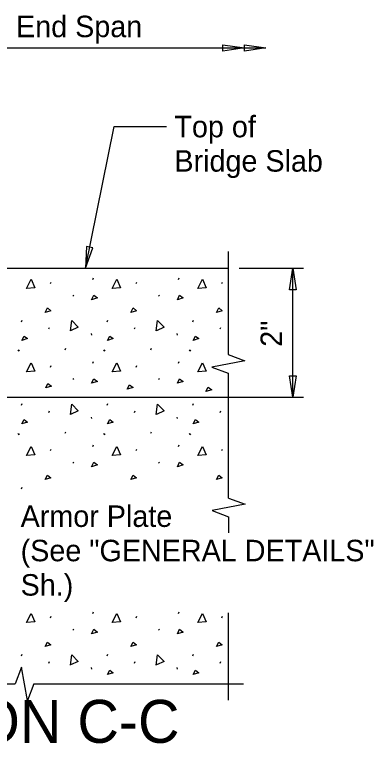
# Model space of a CAD drawing. Extents: x 2799.7 to 2896, y 515.2 to 573.9.
# Drawn here: x 2841.51 to 2847.07, y 530.53 to 541.84 of the extents above; entities that cross this region are included whole.
import ezdxf

# ---------------------------------------------------------------- set-up
doc = ezdxf.new("R2010")
doc.units = 0
for name, color, linetype in [('BR_AUTO DIMENSION', 7, 'Continuous'), ('BR_CONCRETE', 7, 'Continuous'), ('BR_DETAILS', 7, 'Continuous'), ('BR_TEXT', 7, 'Continuous')]:
    doc.layers.add(name, color=color, linetype=linetype)

# ---------------------------------------------------------------- blocks, each defined once
blk = doc.blocks.new('B')
at = {"layer": 'BR_AUTO DIMENSION'}
blk.add_lwpolyline([(-0.2, 0.03), (0, 0), (-0.2, -0.03)], close=True, dxfattribs=at)
blk = doc.blocks.new('ARROW')
at = {"layer": 'BR_AUTO DIMENSION', "xscale": 0.625, "yscale": 0.625}
blk.add_blockref('B', (0, 0), dxfattribs=at)
blk = doc.blocks.new('DAH')
at = {"layer": 'BR_AUTO DIMENSION'}
for p in [(-0.1248, 0), (0, 0)]:
    blk.add_blockref('ARROW', p, dxfattribs=at)

msp = doc.modelspace()

# ---------------------------------------------------------------- linework, layer by layer
at = {"layer": 'BR_AUTO DIMENSION'}
for p, q in [((2834.103, 541.324), (2845.404, 541.324)), ((2842.603, 537.904), (2843.05, 540.103)), ((2843.05, 540.103), (2843.863, 540.103)), ((2844.988, 537.904), (2845.988, 537.904)), ((2845.822, 535.904), (2845.822, 537.904)), ((2840.067, 535.904), (2845.988, 535.904))]:
    msp.add_line(p, q, dxfattribs=at)
for points in [[(2842.62, 538.241), (2842.603, 537.904), (2842.718, 538.221)], [(2845.772, 537.571), (2845.822, 537.904), (2845.872, 537.571)], [(2845.872, 536.237), (2845.822, 535.904), (2845.772, 536.237)]]:
    msp.add_lwpolyline(points, close=True, dxfattribs=at)
at = {"layer": 'BR_CONCRETE'}
msp.add_line((2840.567, 537.904), (2844.821, 537.904), dxfattribs=at)
at = {"layer": 'BR_DETAILS'}
for p, q in [((2844.821, 538.167), (2844.821, 536.565)), ((2842.063, 537.667), (2842.074, 537.691)), ((2842.721, 537.73), (2842.732, 537.755)), ((2843.392, 537.667), (2843.403, 537.691)), ((2844.05, 537.73), (2844.061, 537.755)), ((2844.722, 537.667), (2844.733, 537.691)), ((2842.41, 537.489), (2842.421, 537.472)), ((2843.739, 537.489), (2843.75, 537.472)), ((2841.613, 537.075), (2841.624, 537.1)), ((2842.943, 537.075), (2842.954, 537.1)), ((2844.272, 537.075), (2844.283, 537.1)), ((2842.035, 536.962), (2842.046, 536.987)), ((2843.365, 536.962), (2843.376, 536.987)), ((2844.694, 536.962), (2844.705, 536.987)), ((2842.695, 536.892), (2842.698, 536.867)), ((2844.024, 536.892), (2844.027, 536.867)), ((2841.555, 536.64), (2841.566, 536.623)), ((2841.566, 536.633), (2841.577, 536.617)), ((2842.288, 536.64), (2842.299, 536.665)), ((2842.884, 536.64), (2842.895, 536.623)), ((2842.895, 536.633), (2842.907, 536.617)), ((2843.617, 536.64), (2843.628, 536.665)), ((2844.214, 536.64), (2844.225, 536.623)), ((2844.225, 536.633), (2844.236, 536.617)), ((2842.721, 536.434), (2842.732, 536.459)), ((2844.05, 536.434), (2844.061, 536.459)), ((2842.063, 536.37), (2842.074, 536.395)), ((2843.392, 536.37), (2843.403, 536.395)), ((2842.41, 536.193), (2842.421, 536.176)), ((2843.739, 536.193), (2843.75, 536.176)), ((2844.821, 536.275), (2844.821, 534.337)), ((2841.613, 535.779), (2841.624, 535.804)), ((2842.943, 535.779), (2842.954, 535.804)), ((2844.272, 535.779), (2844.283, 535.804)), ((2842.035, 535.665), (2842.046, 535.69)), ((2843.365, 535.665), (2843.376, 535.69)), ((2844.694, 535.665), (2844.705, 535.69)), ((2842.695, 535.596), (2842.698, 535.571)), ((2844.024, 535.596), (2844.027, 535.571)), ((2841.555, 535.343), (2841.566, 535.327)), ((2841.566, 535.337), (2841.577, 535.32)), ((2842.288, 535.343), (2842.299, 535.368)), ((2842.884, 535.343), (2842.895, 535.327)), ((2842.895, 535.337), (2842.907, 535.32)), ((2843.617, 535.343), (2843.628, 535.368)), ((2844.214, 535.343), (2844.225, 535.327)), ((2844.225, 535.337), (2844.236, 535.32)), ((2842.721, 535.138), (2842.732, 535.163)), ((2844.05, 535.138), (2844.061, 535.163)), ((2842.063, 535.074), (2842.074, 535.099)), ((2843.392, 535.074), (2843.403, 535.099)), ((2844.722, 535.074), (2844.733, 535.099)), ((2842.41, 534.896), (2842.421, 534.88)), ((2843.739, 534.896), (2843.75, 534.88)), ((2841.613, 534.483), (2841.624, 534.508)), ((2844.827, 534.048), (2844.827, 533.796)), ((2842.721, 532.545), (2842.732, 532.57)), ((2844.05, 532.545), (2844.061, 532.57)), ((2842.063, 532.481), (2842.074, 532.506)), ((2843.392, 532.481), (2843.403, 532.506)), ((2844.722, 532.481), (2844.733, 532.506)), ((2844.821, 532.555), (2844.821, 531.203)), ((2842.41, 532.303), (2842.421, 532.287)), ((2843.739, 532.303), (2843.75, 532.287)), ((2841.613, 531.89), (2841.624, 531.915)), ((2842.943, 531.89), (2842.954, 531.915)), ((2844.272, 531.89), (2844.283, 531.915)), ((2842.035, 531.776), (2842.046, 531.801)), ((2843.365, 531.776), (2843.376, 531.801)), ((2844.694, 531.776), (2844.705, 531.801)), ((2842.695, 531.706), (2842.698, 531.681)), ((2844.024, 531.706), (2844.027, 531.681)), ((2837.897, 531.454), (2841.515, 531.454)), ((2841.804, 531.454), (2845.056, 531.454))]:
    msp.add_line(p, q, dxfattribs=at)
for points in [[(2841.688, 537.592), (2841.763, 537.733), (2841.821, 537.603), (2841.691, 537.592)], [(2843.018, 537.592), (2843.093, 537.733), (2843.151, 537.603), (2843.02, 537.592)], [(2844.347, 537.592), (2844.422, 537.733), (2844.48, 537.603), (2844.35, 537.592)], [(2842.701, 537.417), (2842.735, 537.486), (2842.79, 537.444), (2842.701, 537.417)], [(2844.031, 537.417), (2844.064, 537.486), (2844.119, 537.444), (2844.031, 537.417)], [(2841.98, 537.218), (2842.014, 537.288), (2842.069, 537.246), (2841.98, 537.218)], [(2843.31, 537.218), (2843.343, 537.288), (2843.398, 537.246), (2843.31, 537.218)], [(2844.639, 537.218), (2844.672, 537.288), (2844.728, 537.246), (2844.639, 537.218)], [(2842.373, 536.933), (2842.395, 537.092), (2842.494, 536.989), (2842.375, 536.934)], [(2843.702, 536.933), (2843.724, 537.092), (2843.824, 536.989), (2843.705, 536.934)], [(2841.619, 536.784), (2841.652, 536.853), (2841.708, 536.812), (2841.619, 536.784)], [(2842.948, 536.784), (2842.982, 536.853), (2843.037, 536.812), (2842.948, 536.784)], [(2844.278, 536.784), (2844.311, 536.853), (2844.366, 536.812), (2844.278, 536.784)], [(2844.821, 536.565), (2845.078, 536.468), (2844.564, 536.372), (2844.821, 536.275)], [(2841.688, 536.295), (2841.763, 536.437), (2841.821, 536.306), (2841.691, 536.295)], [(2843.018, 536.295), (2843.093, 536.437), (2843.151, 536.306), (2843.02, 536.295)], [(2844.347, 536.295), (2844.422, 536.437), (2844.48, 536.306), (2844.35, 536.295)], [(2842.701, 536.12), (2842.735, 536.19), (2842.79, 536.148), (2842.701, 536.12)], [(2844.031, 536.12), (2844.064, 536.19), (2844.119, 536.148), (2844.031, 536.12)], [(2841.99, 536.048), (2842.023, 536.117), (2842.079, 536.075), (2841.99, 536.048)], [(2843.254, 536.026), (2843.288, 536.095), (2843.343, 536.054), (2843.254, 536.026)], [(2844.475, 535.99), (2844.508, 536.059), (2844.564, 536.018), (2844.475, 535.99)], [(2842.373, 535.637), (2842.395, 535.795), (2842.494, 535.693), (2842.375, 535.637)], [(2843.702, 535.637), (2843.724, 535.795), (2843.824, 535.693), (2843.705, 535.637)], [(2841.619, 535.488), (2841.652, 535.557), (2841.708, 535.515), (2841.619, 535.488)], [(2842.948, 535.488), (2842.982, 535.557), (2843.037, 535.515), (2842.948, 535.488)], [(2844.278, 535.488), (2844.311, 535.557), (2844.366, 535.515), (2844.278, 535.488)], [(2841.688, 534.999), (2841.763, 535.14), (2841.821, 535.01), (2841.691, 534.999)], [(2843.018, 534.999), (2843.093, 535.14), (2843.151, 535.01), (2843.02, 534.999)], [(2844.347, 534.999), (2844.422, 535.14), (2844.48, 535.01), (2844.35, 534.999)], [(2842.701, 534.824), (2842.735, 534.893), (2842.79, 534.852), (2842.701, 534.824)], [(2844.031, 534.824), (2844.064, 534.893), (2844.119, 534.852), (2844.031, 534.824)], [(2841.98, 534.626), (2842.014, 534.695), (2842.069, 534.653), (2841.98, 534.626)], [(2843.31, 534.626), (2843.343, 534.695), (2843.398, 534.653), (2843.31, 534.626)], [(2844.639, 534.626), (2844.672, 534.695), (2844.728, 534.653), (2844.639, 534.626)], [(2844.827, 534.337), (2845.084, 534.241), (2844.57, 534.144), (2844.827, 534.048)], [(2841.688, 532.406), (2841.763, 532.548), (2841.821, 532.417), (2841.691, 532.406)], [(2843.018, 532.406), (2843.093, 532.548), (2843.151, 532.417), (2843.02, 532.406)], [(2844.347, 532.406), (2844.422, 532.548), (2844.48, 532.417), (2844.35, 532.406)], [(2842.701, 532.231), (2842.735, 532.301), (2842.79, 532.259), (2842.701, 532.231)], [(2844.031, 532.231), (2844.064, 532.301), (2844.119, 532.259), (2844.031, 532.231)], [(2841.98, 532.033), (2842.014, 532.102), (2842.069, 532.061), (2841.98, 532.033)], [(2843.31, 532.033), (2843.343, 532.102), (2843.398, 532.061), (2843.31, 532.033)], [(2844.639, 532.033), (2844.672, 532.102), (2844.728, 532.061), (2844.639, 532.033)], [(2842.373, 531.747), (2842.395, 531.906), (2842.494, 531.803), (2842.375, 531.748)], [(2843.702, 531.747), (2843.724, 531.906), (2843.824, 531.803), (2843.705, 531.748)], [(2841.804, 531.454), (2841.708, 531.197), (2841.611, 531.712), (2841.515, 531.454)], [(2842.948, 531.599), (2842.982, 531.668), (2843.037, 531.626), (2842.948, 531.599)], [(2844.278, 531.599), (2844.311, 531.668), (2844.366, 531.626), (2844.278, 531.599)]]:
    msp.add_lwpolyline(points, dxfattribs=at)

# ---------------------------------------------------------------- block references
at = {"layer": 'BR_AUTO DIMENSION', "xscale": 2.6668000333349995, "yscale": 2.6668000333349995}
msp.add_blockref('DAH', (2845.404, 541.324), dxfattribs=at)

# ---------------------------------------------------------------- texts
at = {"layer": 'BR_AUTO DIMENSION'}
msp.add_text('2"', height=0.3334, rotation=90, dxfattribs=at).set_placement((2845.655, 536.686))
at = {"layer": 'BR_TEXT'}
for s, height, p in [('End Span', 0.3333, (2841.528, 541.491)), ('Top of ', 0.3333, (2843.985, 539.937)), ('Bridge Slab', 0.33332, (2843.985, 539.404)), ('Armor Plate', 0.33332, (2841.599, 533.89)), ('(See "GENERAL DETAILS"', 0.33332, (2841.599, 533.357)), ('Sh.)', 0.3333, (2841.599, 532.824)), ('SECTION C-C', 0.66673, (2838.269, 530.539))]:
    msp.add_text(s, height=height, dxfattribs=at).set_placement(p)

doc.saveas('drawing.dxf')
